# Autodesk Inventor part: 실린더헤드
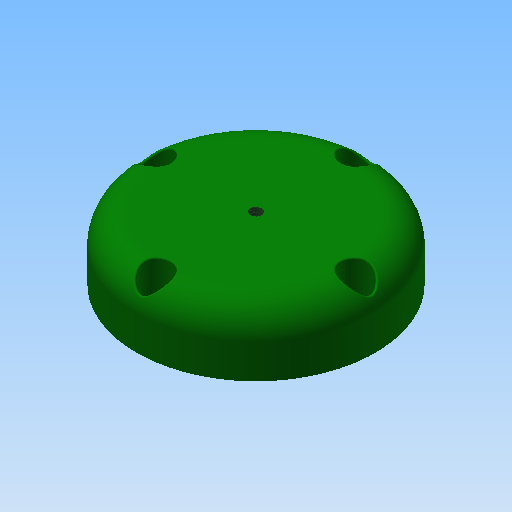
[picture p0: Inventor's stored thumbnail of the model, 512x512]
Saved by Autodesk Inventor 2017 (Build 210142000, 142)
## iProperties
Created: 2016-11
Part Number: 실린더헤드
Material: 알루미늄 6061
Document SubType Name: Modeling
Designer: mduedu
Density: 2.71 g/cm^3
Mass: 235.607 g
Surface Area: 209.259 cm^2
Volume: 86.9399 cm^3
Appearance: 진녹색
Author: mduedu
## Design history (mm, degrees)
sketch "스케치1"
  geometry: C1 r 42 at (0, 0); 1 further point
  constraints: 1 centre point, 1 coincident
  dimensions: "d0" = 84 diameter of C1
extrude "돌출1" new body sketch "스케치1" distance "d1" = 22; taper "d2" = 0 deg
fillet "모깎기1" dims "d3" = 10
sketch "스케치2"
  geometry: C1 r 30 at (0, 0); 1 further point
  constraints: 1 centre point, 1 coincident
  dimensions: "d4" = 60 diameter of C1
extrude "돌출2" join sketch "스케치2" distance "d5" = 5; taper "d6" = 0 deg
sketch "스케치3"
  geometry: C1 r 25 at (0, 0); 1 further point
  constraints: 1 centre point, 1 coincident
  dimensions: "d7" = 50 diameter of C1
extrude "돌출3" cut sketch "스케치3" distance "d8" = 18; taper "d9" = 0 deg
hole "구멍1" diameter "d12" = 4.134; stored, may be unused: countersink angle "d16" = 90 deg, drill point angle "d18" = 118 deg; dims "d10" = 10, "d11" = 10, "d13" = 6, "d14" = 4, "d15" = 2, "d17" = 8
chamfer "모따기1" distance "d19" = 1; stored, may be unused: second distance "d20" = 2, angle "d21" = 45 deg
fillet "모깎기2" dims "d22" = 3
sketch "스케치4"
  geometry: C1 r 17.5 at (0, 0); 1 further point
  constraints: 1 centre point, 1 coincident
  dimensions: "d23" = 35 diameter of C1
extrude "돌출4" cut sketch "스케치4" distance "d24" = 3; taper "d25" = 0 deg
fillet "모깎기3" dims "d26" = 0.5
sketch "스케치5" dims "d32" = 70
  geometry: C1 r 5 at (0, 35); 3 further points
  constraints: 2 coincident, 2 vertical alignment, 1 centre point, 2 other
  dimensions: "d33" = 10 diameter of C1
extrude "돌출5" cut sketch "스케치5" distance "d34" = 12; taper "d35" = 0 deg
sketch "스케치6" dims "d39" = 70
  geometry: 6 further points
  constraints: 2 vertical alignment, 1 coincident, 7 other
  dimensions: "d42" = 360 deg dimension on point (0, -35) point (0, 0) (derived)
sketch "스케치7"
  geometry: 4 further points
  constraints: 4 other
hole "구멍2" sketch "스케치7" at (0, 70), (-35, 35), (35, 35), (0, 0) diameter "d44" = 5.5; stored, may be unused: countersink angle "d48" = 90 deg, drill point angle "d50" = 0 deg; dims "d45" = 6, "d46" = 4, "d47" = 2, "d49" = 8
fillet "모깎기4" dims "d51" = 0.5
chamfer "모따기2" distance "d54" = 5; stored, may be unused: second distance "d55" = 2, angle "d56" = 30 deg
node "솔리드1"
pattern_circular "원형 패턴1" dims angle "d37" = 360 deg
